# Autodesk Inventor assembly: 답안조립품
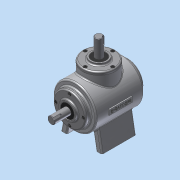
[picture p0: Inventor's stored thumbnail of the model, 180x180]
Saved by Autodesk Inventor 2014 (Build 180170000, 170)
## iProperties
Created: 2015-01
Part Number: 답안조립품
Document SubType Name: Assembly
Designer: user
Author: user
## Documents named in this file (15)
- C:\Users\user\Desktop\450105V1037\답안조립품.iam
- C:\Users\user\Desktop\450105V1037\본체.ipt
- C:\Users\user\Desktop\450105V1037\커버.ipt
- C:\Users\user\Desktop\450105V1037\커버2.ipt
- C:\Users\user\Desktop\450105V1037\M4.ipt
- C:\Users\user\Desktop\450105V1037\베어링 6203.ipt
- C:\Users\user\Desktop\450105V1037\메인 축.ipt
- 메인 축.ipt
- C:\Users\user\Desktop\450105V1037\키 5x5.ipt
- C:\Users\user\Desktop\450105V1037\서브 축.ipt
- 서브 축.ipt
- C:\Users\user\Desktop\450105V1037\키 4x4.ipt
- C:\Users\user\Desktop\450105V1037\메인 베벨기어.ipt
- C:\Users\user\Desktop\450105V1037\서브 베벨기어.ipt
- C:\Users\user\Desktop\450105V1037\오일실.ipt
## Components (12 placed, 1 different names)
1. M4:3 — 각도:1
2. M4:4
3. M4:5
4. M4:6
5. M4:2 — 각도:2
6. M4:7
7. M4:8
8. M4:9
9. M4:1 — 각도:3
10. M4:10
11. M4:11
12. M4:12
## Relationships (3: Angle 3)
- 각도:1 [Angle]: M4:3
- 각도:2 [Angle]: M4:2
- 각도:3 [Angle]: M4:1
